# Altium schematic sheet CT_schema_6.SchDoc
size 293 x 258 mm
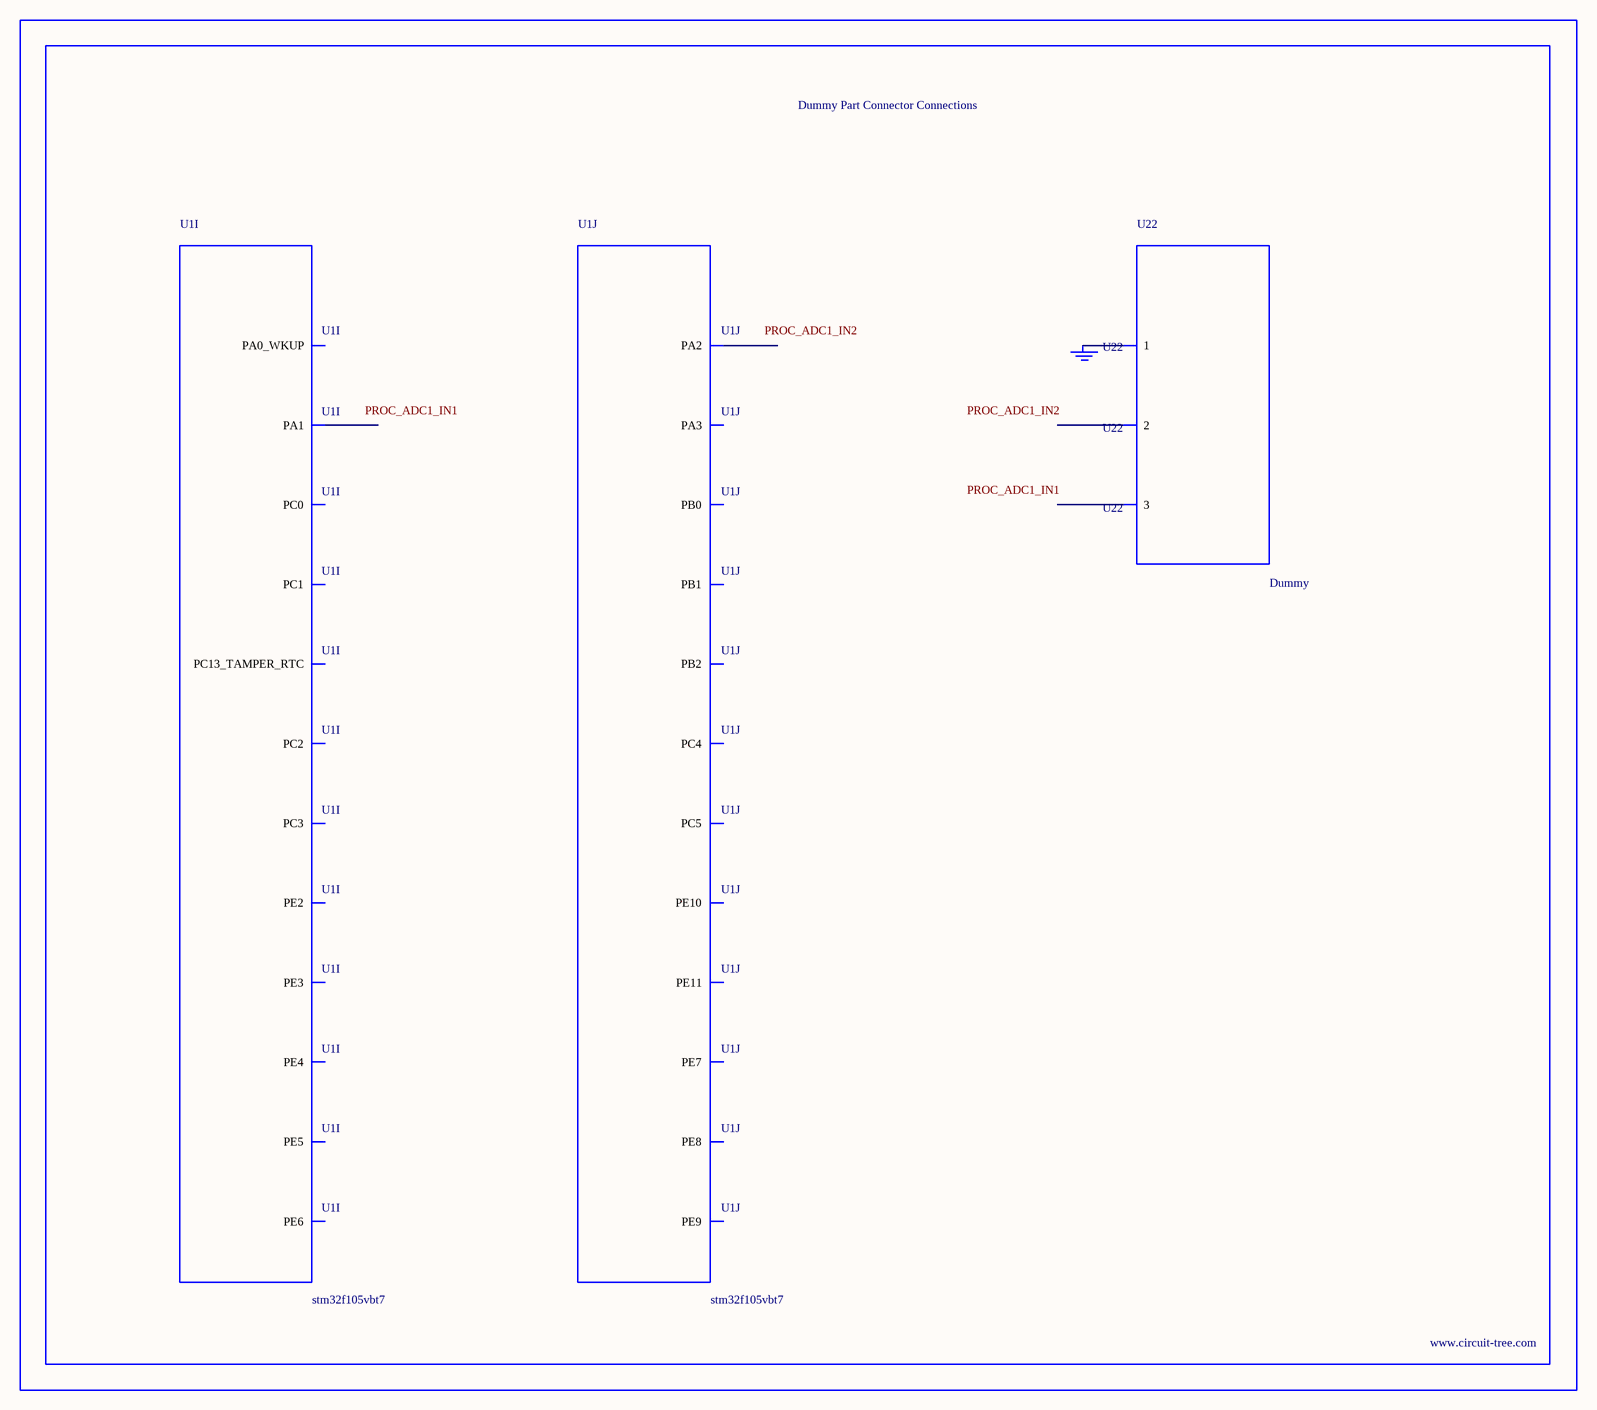
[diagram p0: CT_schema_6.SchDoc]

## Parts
BORDER5  (no value)
GND_INSTANCE_5_0  (no value)
U1  stm32f105vbt7  [LQFP100]  (parts I,J of 10)
U22  Dummy  [DUMMY_PACKAGE_220]

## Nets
NetGND_INSTANCE_5_0_0: GND_INSTANCE_5_0.0(GND) U22.1

Not connected (* = marked no-connect by the designer): U1 1(PE2) 2(PE3) 3(PE4) 4(PE5) 5(PE6) 7(PC13_TAMPER_RTC) 15(PC0) 16(PC1) 17(PC2) 18(PC3) 23(PA0_WKUP) 24(PA1) 25(PA2) 26(PA3) 33(PC4) 34(PC5) 35(PB0) 36(PB1) 37(PB2) 38(PE7) 39(PE8) 40(PE9) 41(PE10) 42(PE11); U22 2 3

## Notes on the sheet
- Labels drawn without touching a wire or pin: PROC_ADC1_IN1, PROC_ADC1_IN2

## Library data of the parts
BORDER5 = BORDER_PAGE5
GND_INSTANCE_5_0 = GND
